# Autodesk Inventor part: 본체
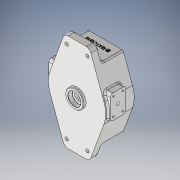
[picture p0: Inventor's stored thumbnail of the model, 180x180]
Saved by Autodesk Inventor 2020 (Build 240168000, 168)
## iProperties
Created: 2023-11
Part Number: 본체
Material: 일반
Document SubType Name: Modeling
Designer: CAD14
Density: 1 g/cm^3
Appearance: 기본값
Mass: 579.61 g
Surface Area: 721.297 cm^2
Volume: 579.61 cm^3
Author: CAD14
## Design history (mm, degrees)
sketch "스케치1"
  geometry: L1 (-24.317, -94)-(24.317, -94); L2 (24.317, -94)-(24.317, 94); L3 (24.317, 94)-(-24.317, 94); L4 (-24.317, 94)-(-24.317, -94); L5 (-24.317, -94)-(24.317, 94); L6 (24.317, -94)-(-24.317, 94); L7 (24.317, 94)-(51.683, 18.811); L8 (0, 0)-(55, 0); L9 (0, 0)-(0, 55); L10 (-24.317, 94)-(-51.683, 18.811); L11 (24.317, -94)-(51.683, -18.811); L12 (-24.317, -94)-(-51.683, -18.811); L13 (-33.78, -68)-(33.78, -68); L14 (33.78, -68)-(33.78, 68); L15 (33.78, 68)-(-33.78, 68); L16 (-33.78, 68)-(-33.78, -68); L17 (-33.78, -68)-(33.78, 68); L18 (33.78, -68)-(-33.78, 68); C1 r 17.5 at (0, 0); A1 r 55 centre (0, 0) between (51.683, 18.811) and (55, 0); 7 further points
  constraints: 36 end point, 4 midpoint, 4 parallel, 3 horizontal, 3 point on circle, 3 symmetric about line, 2 centre point, 2 coincident, 2 perpendicular, 1 point on line, 1 tangent, 1 vertical
  dimensions: "d0" = 110 diameter of A1; "d1" = 188 distance of L1.end L2.end; "d5" = 136 distance of L14.end L13.end; "d8" = 35 diameter of C1; "d109" = 40 deg angle of L7 L10
extrude "돌출1" new body sketch "스케치1" distance "d3" = 15; taper "d4" = 0 deg
extrude "돌출2" join sketch "스케치1" distance "d6" = 55; taper "d7" = 0 deg
extrude "돌출3" join sketch "스케치1" distance "d9" = 5; taper "d10" = 0 deg
sketch "스케치2"
  geometry: C1 r 40 at (0, 9); C2 r 47.5 at (0, 9); C3 r 43.4 at (0, 9); 1 further point
  constraints: 3 centre point, 1 coincident, 1 vertical alignment
  dimensions: "d11" = 80 diameter of C1; "d12" = 9 distance of point (0, 0) C1.centre; "d13" = 95 diameter of C2; "d16" = 4.1 radial gap between concentric circles of C2 C3
sketch "스케치5"
  geometry: L1 (-14, -5)-(32, -5); L2 (32, -5)-(32, -35); L3 (32, -35)-(-14, -35); L4 (-14, -35)-(-14, -5); L5 (-14, -5)-(32, -35); L6 (32, -5)-(-14, -35); L7 (94, 0)-(18.811, 0) reference; 3 further points
  constraints: 12 end point, 3 midpoint, 2 parallel, 1 horizontal, 1 perpendicular
  dimensions: "d23" = 46 distance of L2.end L3.end; "d24" = 30 distance of L1.end L2.end; "d54" = 9 horizontal distance of point (0, 0) point (9, -20); "d55" = 20 vertical distance of point (9, -20) point (0, 0)
extrude "돌출7" join sketch "스케치5" stored distance "d27" = 118; taper "d28" = 0 deg
extrude "돌출4" cut sketch "스케치2" distance "d14" = 30; taper "d15" = 0 deg
extrude "돌출5" cut sketch "스케치2" distance "d17" = 2.4; taper "d18" = 0 deg
sketch "스케치3"
  geometry: C1 r 10 at (0, -9); 1 further point
  constraints: 1 centre point, 1 coincident
  dimensions: "d19" = 20 diameter of C1
extrude "돌출6" cut sketch "스케치3" distance "d20" = 10; taper "d21" = 0 deg
sketch "스케치4"
  geometry: C1 r 8 at (0, 0); 1 further point
  constraints: 1 centre point, 1 coincident
  dimensions: "d22" = 16 diameter of C1
extrude "돌출8" cut sketch "스케치4" distance "d29" = 11.6; taper "d30" = 0 deg
sketch "스케치6"
  geometry: C1 r 17.5 at (0, 0) reference; 2 further points
  constraints: 1 coincident
hole "구멍1" sketch "스케치6" at (0, 0) diameter "d31" = 25; stored, may be unused: countersink angle "d35" = 90 deg, drill point angle "d37" = 0 deg; dims "d32" = 6, "d33" = 4, "d34" = 2, "d36" = 8.4
sketch "스케치7"
  geometry: L1 (-29, 0)-(29, 0); L2 (-29, 6)-(29, 6); L3 (-29, -6)-(29, -6); L4 (-29, 17)-(29, 17); L5 (0, -9)-(0, 38.035); L6 (-15, 17)-(15, 17); C1 r 24 at (0, -9); A1 r 29 centre (0, 0) between (-28.566, 5) and (28.566, 5); 12 further points
  constraints: 12 end point, 4 point on circle, 3 parallel, 2 centre point, 2 horizontal, 2 midpoint, 1 coincident, 1 vertical, 1 vertical alignment
  dimensions: "d38" = 58 diameter of A1; "d39" = 9 distance of A1.centre point (0, -9); "d40" = 48 diameter of C1; "d45" = 9 distance from line of point (0, -9) L1; "d46" = 6 distance between parallel lines of L1 L2; "d47" = 6 distance between parallel lines of L1 L3; "d48" = 17 distance between parallel lines of L4 L1; "d49" = 30 distance of L6.start L6.end
extrude "돌출10" cut sketch "스케치7" distance "d50" = 12; taper "d51" = 0 deg
fillet "모깎기2" dims "d52" = 2
fillet "모깎기3" dims "d53" = 2
sketch "스케치9"
  geometry: L1 (0, 0)-(20, 0); L2 (20, 0)-(20, 9); L3 (20, 9)-(0, 9); L4 (0, 9)-(0, 0); L5 (11, -8)-(29, -8); L6 (29, -8)-(29, 26); L7 (29, 26)-(11, 26); L8 (11, 26)-(11, -8); L9 (11, -8)-(29, 26); L10 (29, -8)-(11, 26); C1 r 3 at (20, 9)
  constraints: 20 end point, 4 parallel, 2 horizontal, 2 midpoint, 2 perpendicular, 1 centre point, 1 coincident
  dimensions: "d56" = 20 distance of L3.end L2.end; "d57" = 9 distance of L2.end L1.end; "d58" = 6 diameter of C1; "d61" = 18 distance of L7.end L6.end; "d62" = 34 distance of L6.end L5.end
extrude "돌출11" cut sketch "스케치9" stored distance "d59" = 12; taper "d60" = 0 deg
hole "구멍2" sketch "스케치7" diameter "d63" = 3.242; stored, may be unused: countersink angle "d67" = 90 deg, drill point angle "d69" = 118 deg; dims "d64" = 8, "d65" = 4, "d66" = 2, "d68" = 10
hole "구멍3" sketch "스케치9" diameter "d70" = 3.242; stored, may be unused: countersink angle "d74" = 90 deg, drill point angle "d76" = 118 deg; dims "d71" = 8, "d72" = 4, "d73" = 2, "d75" = 10
sketch "스케치10"
  geometry: L1 (-20, -79)-(20, -79); L2 (20, -79)-(20, 79); L3 (20, 79)-(-20, 79); L4 (-20, 79)-(-20, -79); L5 (-20, -79)-(20, 79); L6 (20, -79)-(-20, 79); C1 r 12.5 at (0, 0) reference; 1 further point
  constraints: 12 end point, 2 midpoint, 2 parallel, 1 horizontal, 1 perpendicular
  dimensions: "d77" = 40 distance of L3.end L2.end; "d78" = 158 distance of L2.end L1.end
hole "구멍4" sketch "스케치10" at (-20, -79), (20, -79), (-20, 79), (20, 79) diameter "d79" = 6.6; stored, may be unused: countersink angle "d83" = 90 deg, drill point angle "d85" = 118 deg; dims "d80" = 8, "d81" = 11, "d82" = 6.6, "d84" = 15
sketch "스케치11"
  geometry: L1 (-25, -61)-(25, -61); L2 (25, -61)-(25, 61); L3 (25, 61)-(-25, 61); L4 (-25, 61)-(-25, -61); L5 (-25, -61)-(25, 61); L6 (25, -61)-(-25, 61); C1 r 10 at (0, 0) reference; 1 further point
  constraints: 12 end point, 2 midpoint, 2 parallel, 1 horizontal, 1 perpendicular
  dimensions: "d86" = 50 distance of L3.end L2.end; "d87" = 122 distance of L2.end L1.end
hole "구멍5" sketch "스케치11" at (25, 61), (-25, 61), (-25, -61), (25, -61) diameter "d88" = 4.917; stored, may be unused: countersink angle "d92" = 90 deg, drill point angle "d94" = 118 deg; dims "d89" = 12, "d90" = 11, "d91" = 6.6, "d93" = 14
sketch "스케치12"
  geometry: L1 (12.5, 5)-(12.5, 12.599); L2 (-12.5, 5)-(12.5, 5) reference; L3 (17.5, 5)-(-17.5, 5) reference; L4 (12.5, 5)-(12.5, 4.6); L5 (12.5, -3.4)-(12.5, 5) reference; L6 (12.5, 4.6)-(13.235, 5.873); L7 (12.5, 5)-(12.731, 5); L8 (0, 5)-(0, 2.376); 1 further point
  constraints: 10 end point, 3 point on line, 2 vertical, 1 midpoint
  dimensions: "d97" = 0.4 distance of L1.start L4.end; "d98" = 30 deg angle of L6 L4
revolve "회전1" sketch "스케치12" stored, may be unused: angle "d99" = 90 deg
fillet "모깎기4" dims "d100" = 0.2
fillet "모깎기5" dims "d101" = 0.5
fillet "모깎기6" dims "d102" = 10
fillet "모깎기7" dims "d103" = 5
fillet "모깎기8" dims "d104" = 3
fillet "모깎기9" dims "d105" = 3
sketch "스케치13"
  geometry: L1 (63.358, 0)-(0, 0) reference; L2 (0, 37)-(63.358, 37) reference; 3 further points
  constraints: 1 midpoint, 1 vertical alignment, 1 other
  dimensions: "d113" = 15 distance from line of L2 point (31.679, 22)
feature "엠보싱1" sketch "스케치13" dims "d107" = 0.5, "d108" = 0
chamfer "모따기1" distance "d110" = 1; stored, may be unused: second distance "d111" = 2, angle "d112" = 45 deg
feature "분할1"
node "솔리드1"
mirror "미러1"
mirror "미러2"
feature "A9D066F2-1C7D-4E18-AEED-F7BC21143FA4" dims "d31" = 25, "d32" = 6, "d33" = 4, "d34" = 2, "d35" = 90 deg, "d36" = 8.4, "d37" = 0
